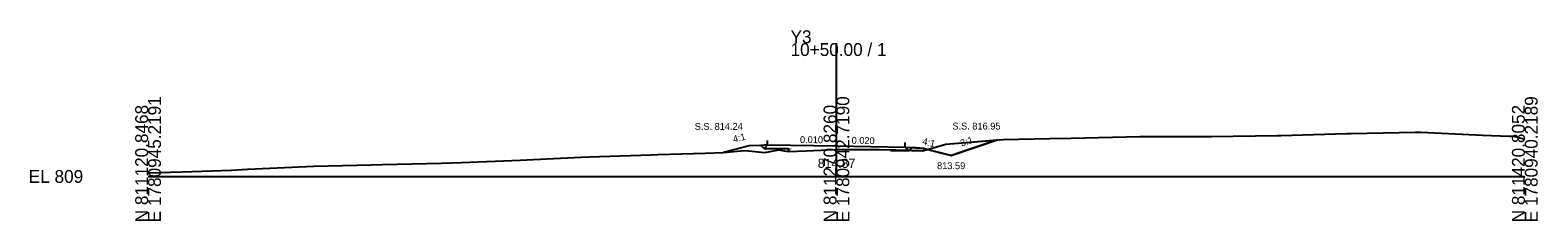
# Model space of a CAD drawing. Extents: x -26 to 303, y -10 to 4017.
# Drawn here: x -25.7 to 302.8, y 990.3 to 1031.9 of the extents above; entities that cross this region are included whole.
import ezdxf

# ---------------------------------------------------------------- set-up
doc = ezdxf.new("R2010")
doc.units = 0
for name, color, linetype in [('Exist Cross Section Cell', 7, 'Continuous'), ('Exist XS Center Line Elevation Label', 7, 'Continuous'), ('Exist XS Ground Line', 7, 'Continuous'), ('Prop XS Ditch Slope Text', 7, 'Continuous'), ('Prop XS Ditch Standard Text', 7, 'Continuous'), ('Prop XS Dump Level', 7, 'Continuous'), ('Prop XS Earthwork Shape', 7, 'Continuous'), ('Prop XS EOT Tick Mark', 7, 'Continuous'), ('Prop XS Finish Grade', 7, 'Continuous'), ('Prop XS Finish Grade Earthwork', 7, 'Continuous'), ('Prop XS Finish Grade Pavement', 7, 'Continuous'), ('Prop XS Pvmt Edge Slope', 7, 'Continuous'), ('Prop XS SE Text', 7, 'Continuous'), ('Prop XS Side Slope Text', 7, 'Continuous'), ('Prop XS SS Elevation Text', 7, 'Continuous'), ('Prop XS Subgrade Earthwork', 7, 'Continuous')]:
    doc.layers.add(name, color=color, linetype=linetype)

msp = doc.modelspace()

# ---------------------------------------------------------------- linework, layer by layer
at = {"layer": 'Exist Cross Section Cell'}
for p, q in [((150, 1000), (150, 1029.07)), ((0, 1000), (150, 1000)), ((150, 1000), (300, 1000))]:
    msp.add_line(p, q, dxfattribs=at)
at = {"layer": 'Exist XS Ground Line'}
for p, q in [((201.16, 1008.36), (216.11, 1008.69)), ((216.11, 1008.69), (216.41, 1008.69)), ((216.41, 1008.69), (231.11, 1008.72)), ((231.11, 1008.72), (231.67, 1008.72)), ((231.67, 1008.72), (246.12, 1008.93)), ((246.12, 1008.93), (246.92, 1008.93)), ((246.92, 1008.93), (261.12, 1009.35)), ((261.12, 1009.35), (262.18, 1009.35)), ((262.18, 1009.35), (276.12, 1009.69)), ((276.12, 1009.69), (277.44, 1009.66)), ((277.44, 1009.66), (290.75, 1009)), ((290.75, 1009), (296.65, 1008.8)), ((296.65, 1008.8), (297.59, 1008.76)), ((297.59, 1008.76), (300, 1008.16)), ((125.39, 1005.24), (129.92, 1005.63)), ((129.92, 1005.63), (130.85, 1005.55)), ((130.85, 1005.55), (134.42, 1005.25)), ((134.42, 1005.25), (135.53, 1005.46)), ((135.53, 1005.46), (137.42, 1005.82)), ((137.42, 1005.82), (138.63, 1005.6)), ((138.63, 1005.6), (139.52, 1005.45)), ((139.52, 1005.45), (143.43, 1005.61)), ((143.43, 1005.61), (146.68, 1005.74)), ((146.68, 1005.74), (147.83, 1005.78)), ((147.83, 1005.78), (150, 1005.87)), ((150, 1005.87), (150.83, 1005.9)), ((150.83, 1005.9), (154.12, 1005.87)), ((154.12, 1005.87), (154.83, 1005.88)), ((154.83, 1005.88), (159.31, 1005.84)), ((159.31, 1005.84), (162.93, 1005.81)), ((162.93, 1005.81), (166.43, 1005.69)), ((166.43, 1005.69), (168.07, 1005.63)), ((168.07, 1005.63), (168.76, 1005.6)), ((168.76, 1005.6), (169.56, 1005.83)), ((169.56, 1005.83), (173.86, 1007.02)), ((173.86, 1007.02), (186.35, 1008.05)), ((186.35, 1008.05), (196.52, 1008.27)), ((196.52, 1008.27), (201.16, 1008.36)), ((24.95, 1001.7), (36.12, 1002.24)), ((36.12, 1002.24), (48.63, 1002.53)), ((48.63, 1002.53), (51.09, 1002.57)), ((51.09, 1002.57), (63.85, 1002.91)), ((63.85, 1002.91), (66.09, 1002.94)), ((66.09, 1002.94), (68.31, 1003.03)), ((68.31, 1003.03), (81.1, 1003.57)), ((81.1, 1003.57), (94.33, 1004.21)), ((94.33, 1004.21), (96.09, 1004.3)), ((96.09, 1004.3), (109.62, 1004.7)), ((109.62, 1004.7), (111.1, 1004.75)), ((111.1, 1004.75), (121.37, 1005.06)), ((121.37, 1005.06), (125.39, 1005.24)), ((0, 1000.82), (7.35, 1000.98)), ((7.35, 1000.98), (18.16, 1001.4)), ((18.16, 1001.4), (21.69, 1001.56)), ((21.69, 1001.56), (24.95, 1001.7))]:
    msp.add_line(p, q, dxfattribs=at)
at = {"layer": 'Prop XS Dump Level'}
for p, q in [((135, 1006.86), (150, 1006.71)), ((150, 1006.71), (165, 1006.41))]:
    msp.add_line(p, q, dxfattribs=at)
at = {"layer": 'Prop XS Earthwork Shape'}
for points in [[(125.33, 1005.24), (125.39, 1005.24), (129.92, 1005.63), (130.85, 1005.55), (134.42, 1005.25), (135.53, 1005.46), (137.42, 1005.82), (138.63, 1005.6), (139.52, 1005.45), (139.52, 1006.02), (134.22, 1006.07), (133.51, 1006.78), (131, 1006.66)], [(161.85, 1005.82), (162.93, 1005.81), (165.92, 1005.71), (165.81, 1005.6), (161.85, 1005.68)], [(165.92, 1005.71), (166.43, 1005.69), (168.07, 1005.63), (168.76, 1005.6), (169.56, 1005.83), (169.77, 1005.89), (169, 1006.09), (166.5, 1006.29)], [(169.77, 1005.89), (173.86, 1007.02), (185.08, 1007.95), (175, 1004.59)]]:
    msp.add_lwpolyline(points, close=True, dxfattribs=at)
at = {"layer": 'Prop XS EOT Tick Mark'}
for p, q in [((135, 1006.86), (135, 1007.86)), ((165, 1006.41), (165, 1007.41))]:
    msp.add_line(p, q, dxfattribs=at)
at = {"layer": 'Prop XS Finish Grade'}
for p, q in [((135, 1006.86), (133.51, 1006.78)), ((165, 1006.41), (166.5, 1006.29))]:
    msp.add_line(p, q, dxfattribs=at)
at = {"layer": 'Prop XS Finish Grade Earthwork'}
for p, q in [((131, 1006.66), (125.33, 1005.24)), ((133.51, 1006.78), (131, 1006.66)), ((166.5, 1006.29), (169, 1006.09)), ((169, 1006.09), (175, 1004.59)), ((175, 1004.59), (185.08, 1007.95))]:
    msp.add_line(p, q, dxfattribs=at)
at = {"layer": 'Prop XS Finish Grade Pavement'}
for p, q in [((135, 1006.86), (150, 1006.71)), ((150, 1006.71), (165, 1006.41))]:
    msp.add_line(p, q, dxfattribs=at)
at = {"layer": 'Prop XS Pvmt Edge Slope'}
for p, q in [((135, 1006.86), (134.22, 1006.07)), ((165, 1006.41), (165.81, 1005.6))]:
    msp.add_line(p, q, dxfattribs=at)
at = {"layer": 'Prop XS Subgrade Earthwork'}
for p, q in [((134.22, 1006.07), (133.51, 1006.78)), ((134.22, 1006.07), (139.52, 1006.02)), ((139.52, 1006.02), (139.52, 1005.45)), ((161.85, 1005.82), (161.85, 1005.68)), ((161.85, 1005.68), (165.81, 1005.6)), ((165.81, 1005.6), (166.5, 1006.29))]:
    msp.add_line(p, q, dxfattribs=at)

# ---------------------------------------------------------------- texts
at = {"layer": 'Exist Cross Section Cell'}
for s, p in [('Y3', (140, 1029.07)), ('10+50.00 / 1', (140, 1026.27)), ('EL 809', (-26, 998.6))]:
    msp.add_text(s, height=2.8, dxfattribs=at).set_placement(p)
for s, p in [('N 811120.8468', (0, 990)), ('E 1780945.2191', (2.8, 990)), ('N 811270.8260', (150, 990)), ('E 1780942.7190', (152.8, 990)), ('N 811420.8052', (300, 990)), ('E 1780940.2189', (302.8, 990))]:
    msp.add_text(s, height=2.8, rotation=90, dxfattribs=at).set_placement(p)
at = {"layer": 'Exist XS Center Line Elevation Label'}
msp.add_text('814.87', height=2, dxfattribs=at).set_placement((145.94, 1001.87))
at = {"layer": 'Prop XS Ditch Slope Text'}
for rotation, p in [(14.0362, (127.64, 1007.36)), (345.9638, (168.59, 1007.01))]:
    msp.add_text('4:1', height=1.5, rotation=rotation, dxfattribs=at).set_placement(p)
at = {"layer": 'Prop XS Ditch Standard Text'}
msp.add_text('813.59', height=1.5, dxfattribs=at).set_placement((171.93, 1001.59))
at = {"layer": 'Prop XS Dump Level'}
for s, height, p in [('Case1', 0.04, (131, 1006.62)), ('Eop', 0.3, (139.52, 1005.89)), ('Eop', 0.3, (166.09, 1005.45)), ('Case1', 0.04, (169, 1006.05))]:
    msp.add_text(s, height=height, dxfattribs=at).set_placement(p)
at = {"layer": 'Prop XS SE Text'}
for s, rotation, p in [('0.010', 359.4271, (142.05, 1007.29)), ('0.020', 358.8542, (153.3, 1007.14))]:
    msp.add_text(s, height=1.5, rotation=rotation, dxfattribs=at).set_placement(p)
at = {"layer": 'Prop XS Side Slope Text'}
msp.add_text('3:1', height=1.5, rotation=18.4349, dxfattribs=at).set_placement((177.29, 1006.51))
at = {"layer": 'Prop XS SS Elevation Text'}
for s, p in [('S.S. 814.24', (119.11, 1010.15)), ('S.S. 816.95', (175.27, 1010.23))]:
    msp.add_text(s, height=1.5, dxfattribs=at).set_placement(p)

doc.saveas('drawing.dxf')
